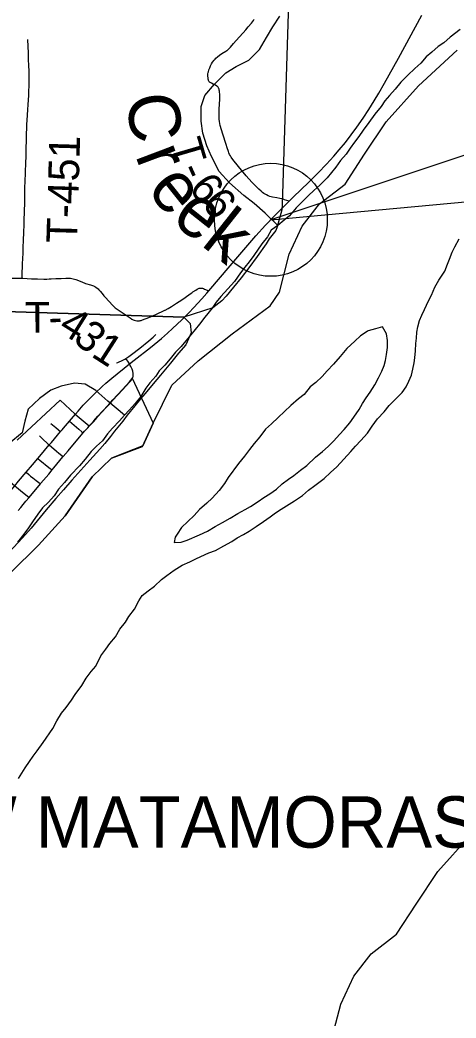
# Model space of a CAD drawing. Extents: x 6.3 to 40.3, y 9 to 31.
# Drawn here: x 11.78 to 12.585, y 24.889 to 26.729 of the extents above; entities that cross this region are included whole.
import ezdxf

# ---------------------------------------------------------------- set-up
doc = ezdxf.new("R2010")
doc.units = 0
for name, color, linetype in [('Default', 7, 'Continuous'), ('GM_X_City_Street', 7, 'Continuous'), ('GM_X_Corporation', 7, 'Continuous'), ('GM_X_Corporation_Text', 7, 'Continuous'), ('GM_X_Major_River', 7, 'Continuous'), ('GM_X_Minor_River', 7, 'Continuous'), ('GM_X_Minor_River_Text', 7, 'Continuous'), ('GM_X_Section', 7, 'Continuous'), ('GM_X_State_Route', 7, 'Continuous'), ('GM_X_Township_Road', 7, 'Continuous'), ('GM_X_Township_Road_Text', 7, 'Continuous'), ('SH_Cut_Line', 7, 'Continuous'), ('TX_P_1', 7, 'Continuous')]:
    doc.layers.add(name, color=color, linetype=linetype)

msp = doc.modelspace()

# ---------------------------------------------------------------- linework, layer by layer
at = {"layer": 'Default'}
for points in [[(11.7623, 25.7099), (11.814, 25.7608), (11.8637, 25.8147), (11.9131, 25.8868), (11.949, 25.9211), (12.0064, 25.9429), (12.0259, 25.9857), (12.0606, 26.0557), (12.1089, 26.1009), (12.1716, 26.1508), (12.2422, 26.2023), (12.2589, 26.2273), (12.2772, 26.2974), (12.3007, 26.349), (12.3328, 26.3901), (12.3801, 26.4265), (12.4161, 26.4817), (12.4558, 26.5416), (12.5156, 26.6082), (12.5871, 26.6738)], [(12.3542, 24.8446), (12.3726, 24.9147), (12.3961, 24.9663), (12.4281, 25.0074), (12.4754, 25.0438), (12.5114, 25.0991), (12.5512, 25.1589), (12.6109, 25.2255)]]:
    msp.add_lwpolyline(points, dxfattribs=at)
at = {"layer": 'GM_X_City_Street'}
for points in [[(11.8714, 25.9895), (11.8758, 25.9857), (11.8884, 25.975), (11.8945, 25.9698), (11.8968, 25.9679)], [(11.7768, 25.8248), (11.7815, 25.8304), (11.7859, 25.8356), (11.791, 25.8418), (11.797, 25.8489), (11.7993, 25.8517), (11.8059, 25.8598), (11.8177, 25.8739), (11.8186, 25.875), (11.833, 25.8921), (11.8392, 25.8995), (11.8426, 25.9035), (11.8594, 25.9235), (11.8599, 25.9241), (11.8688, 25.935), (11.887, 25.9563), (11.8968, 25.9679), (11.8994, 25.9709), (11.9053, 25.9774), (11.908, 25.9804)], [(11.837, 25.985), (11.8464, 25.9776), (11.8512, 25.9736), (11.855, 25.9704)], [(11.8158, 25.9625), (11.8212, 25.9574), (11.8323, 25.9474), (11.8342, 25.9457), (11.8473, 25.9344), (11.852, 25.9305), (11.8571, 25.9264), (11.8599, 25.9241)], [(11.8128, 25.9206), (11.8172, 25.9169), (11.8196, 25.915), (11.8301, 25.9065), (11.8359, 25.902), (11.8392, 25.8995)], [(11.746, 25.89), (11.7467, 25.8899), (11.7473, 25.8897), (11.7483, 25.8891), (11.749, 25.8885), (11.7618, 25.8776), (11.7704, 25.8704), (11.7737, 25.8676), (11.7809, 25.8617), (11.7877, 25.8564), (11.7932, 25.852), (11.797, 25.8489)], [(11.7914, 25.8953), (11.7961, 25.8914), (11.7996, 25.8884), (11.804, 25.885), (11.8097, 25.8804), (11.8147, 25.8764), (11.8177, 25.8739)]]:
    msp.add_lwpolyline(points, dxfattribs=at)
at = {"layer": 'GM_X_Corporation'}
msp.add_lwpolyline([(11.775, 25.9545), (11.8544, 26.0285), (11.8821, 26.0027), (11.9078, 25.9809), (11.9103, 25.9835), (11.912, 25.9852), (11.9149, 25.9884), (11.9197, 25.9939), (11.9238, 25.9985), (11.9318, 26.0072), (11.9439, 26.0205), (11.9514, 26.0287), (11.9692, 26.0478), (11.9821, 26.062), (11.9848, 26.0653), (11.9863, 26.0673), (11.9871, 26.0687), (12.0259, 25.9857), (12.0067, 25.9443), (11.955, 25.9235), (11.949, 25.9211), (11.9131, 25.8868), (11.8637, 25.8147), (11.814, 25.7608), (11.7623, 25.7099)], dxfattribs=at)
at = {"layer": 'GM_X_Major_River'}
for points in [[(12.5927, 26.7118), (12.574, 26.6974), (12.5624, 26.6874), (12.5523, 26.6804), (12.5407, 26.6703), (12.5299, 26.6614), (12.5202, 26.6498), (12.509, 26.6397), (12.4963, 26.6277), (12.4833, 26.6146), (12.4725, 26.6019), (12.4621, 26.59), (12.4536, 26.5803), (12.4469, 26.57), (12.4354, 26.5557), (12.4239, 26.5403), (12.4136, 26.5261), (12.4058, 26.5142), (12.3976, 26.5038), (12.3895, 26.493), (12.3821, 26.4819), (12.3717, 26.47), (12.3632, 26.4577), (12.3554, 26.448), (12.3472, 26.4384), (12.3338, 26.4245), (12.3226, 26.4152), (12.3129, 26.4059), (12.3025, 26.3951), (12.2902, 26.3831), (12.2779, 26.3681), (12.2679, 26.36), (12.2563, 26.3503), (12.2435, 26.3417), (12.2369, 26.3294), (12.2265, 26.3164), (12.2118, 26.2949), (12.2029, 26.2833), (12.1954, 26.2733), (12.1869, 26.2629), (12.1758, 26.2468), (12.1639, 26.2337), (12.1509, 26.2194), (12.142, 26.209), (12.1346, 26.1979), (12.1216, 26.1813), (12.1112, 26.1682), (12.1034, 26.1586), (12.0956, 26.1486), (12.0864, 26.1378), (12.0774, 26.127), (12.067, 26.1166), (12.0574, 26.1043), (12.0473, 26.0931), (12.0369, 26.0823), (12.031, 26.0723), (12.0199, 26.0604), (12.0121, 26.0504), (12.0029, 26.035), (11.9928, 26.0223), (11.9817, 26.01), (11.9731, 26.0004), (11.9635, 25.9903), (11.9508, 25.9764), (11.9415, 25.966), (11.9323, 25.9533), (11.9214, 25.9437), (11.9114, 25.9336), (11.9002, 25.9194), (11.8902, 25.9071), (11.8731, 25.8897), (11.862, 25.8762), (11.8512, 25.8643), (11.843, 25.8516), (11.8326, 25.8404), (11.8218, 25.8296)], [(11.9561, 25.592), (11.9645, 25.6058), (11.9749, 25.6189), (11.9812, 25.6292), (11.9916, 25.6427), (11.9996, 25.658), (12.0055, 25.668), (12.0164, 25.6769), (12.0284, 25.6851), (12.041, 25.6978), (12.0511, 25.7048), (12.0646, 25.7145), (12.0796, 25.7239), (12.0939, 25.7302), (12.1044, 25.7354), (12.1142, 25.7397), (12.1289, 25.7468), (12.1409, 25.7512), (12.1563, 25.7598), (12.1714, 25.7677), (12.1811, 25.7747), (12.1928, 25.7806), (12.2029, 25.7868), (12.216, 25.7954), (12.2299, 25.8044), (12.2422, 25.8134), (12.252, 25.8204), (12.2621, 25.827), (12.2771, 25.8367), (12.2868, 25.8426), (12.3014, 25.8527), (12.3126, 25.862), (12.3246, 25.8706), (12.3418, 25.8838), (12.3534, 25.895), (12.365, 25.9055), (12.378, 25.9194), (12.3906, 25.9336), (12.3992, 25.9436), (12.4092, 25.9537), (12.4215, 25.9676), (12.4304, 25.9806), (12.44, 25.9937), (12.4527, 26.0068), (12.4616, 26.0184), (12.4757, 26.0327), (12.4854, 26.0423), (12.4928, 26.0531), (12.4979, 26.063), (12.5027, 26.0745), (12.5055, 26.0852), (12.5076, 26.097), (12.5089, 26.1065), (12.5102, 26.1194), (12.5111, 26.1327), (12.5121, 26.1429), (12.513, 26.1536), (12.5147, 26.1635), (12.5179, 26.1749), (12.5219, 26.1848), (12.5267, 26.1955), (12.5344, 26.2116), (12.5395, 26.2216), (12.5461, 26.2365), (12.5534, 26.2495), (12.5641, 26.266), (12.5692, 26.279), (12.5732, 26.2885), (12.5779, 26.3012), (12.583, 26.3111), (12.5911, 26.3257)], [(12.0666, 25.7756), (12.0645, 25.7661), (12.0774, 25.7667), (12.0887, 25.7704), (12.1112, 25.7799), (12.1263, 25.7866), (12.1402, 25.7952), (12.1537, 25.8026), (12.1683, 25.8109), (12.1822, 25.8195), (12.1957, 25.8265), (12.2055, 25.8324), (12.2197, 25.8414), (12.2302, 25.8488), (12.2411, 25.8558), (12.2538, 25.8644), (12.2639, 25.874), (12.2755, 25.8826), (12.2856, 25.8892), (12.298, 25.8993), (12.3099, 25.9079), (12.3256, 25.923), (12.3387, 25.9334), (12.3491, 25.9431), (12.3596, 25.9532), (12.37, 25.9647), (12.3785, 25.9744), (12.3893, 25.9867), (12.3963, 25.9967), (12.406, 26.0109), (12.4126, 26.0224), (12.4192, 26.0328), (12.4266, 26.0431), (12.4351, 26.0566), (12.4417, 26.0696), (12.4483, 26.0818), (12.4523, 26.0922), (12.4548, 26.1017), (12.4569, 26.1127), (12.4585, 26.1253), (12.4587, 26.1382), (12.457, 26.1503), (12.4495, 26.1634), (12.4363, 26.1601), (12.4231, 26.1562)], [(12.4231, 26.1562), (12.4212, 26.1549), (12.4089, 26.1471), (12.3984, 26.1371), (12.3835, 26.1235), (12.3712, 26.1089), (12.359, 26.0946), (12.3471, 26.0823), (12.3378, 26.0719), (12.3262, 26.061), (12.3157, 26.0529), (12.305, 26.039), (12.2941, 26.0309), (12.2803, 26.0185), (12.2684, 26.0073), (12.2564, 25.9964), (12.2441, 25.9848), (12.2333, 25.9748), (12.2229, 25.9609), (12.2125, 25.9486), (12.2036, 25.9374), (12.1944, 25.9247), (12.1832, 25.9116), (12.1644, 25.8855), (12.1574, 25.8744), (12.1477, 25.8617), (12.1347, 25.8478), (12.125, 25.8385), (12.1116, 25.8265), (12.1015, 25.8153), (12.09, 25.8045), (12.0784, 25.7933), (12.0703, 25.781), (12.0666, 25.7756)], [(11.8218, 25.8296), (11.8129, 25.8181), (11.8033, 25.8038), (11.7956, 25.7927), (11.7874, 25.7812), (11.7755, 25.7662)], [(11.7775, 25.3308), (11.7893, 25.3504), (11.7978, 25.3619), (11.8041, 25.3715), (11.8119, 25.3819), (11.823, 25.3969), (11.8407, 25.423), (11.8481, 25.4368), (11.8569, 25.451), (11.8651, 25.4617), (11.8751, 25.4752), (11.8817, 25.4852), (11.8943, 25.5021), (11.9021, 25.5155), (11.9117, 25.5282), (11.9202, 25.5378), (11.929, 25.557), (11.9383, 25.5689), (11.946, 25.5796), (11.9561, 25.592)]]:
    msp.add_lwpolyline(points, dxfattribs=at)
at = {"layer": 'GM_X_Minor_River'}
for points in [[(12.2563, 26.3503), (12.2324, 26.373), (12.2123, 26.3907), (12.193, 26.4055), (12.1669, 26.4289), (12.1476, 26.45), (12.1336, 26.4776), (12.1249, 26.4972), (12.1177, 26.5206), (12.1143, 26.5429), (12.1146, 26.5697), (12.1211, 26.5904), (12.1393, 26.6112), (12.1601, 26.6319), (12.1794, 26.6433), (12.2025, 26.655), (12.2222, 26.675), (12.235, 26.6969), (12.2471, 26.7169), (12.2596, 26.7361)], [(11.9731, 26.0004), (11.942, 26.0262), (11.9201, 26.0462), (11.9004, 26.0575), (11.8807, 26.0598), (11.8561, 26.0538), (11.8368, 26.0466), (11.816, 26.0315), (11.7952, 26.0115), (11.7891, 25.9896), (11.7842, 25.9681), (11.7603, 25.9481)]]:
    msp.add_lwpolyline(points, dxfattribs=at)
at = {"layer": 'GM_X_Section'}
msp.add_lwpolyline([(11.3031, 27.2038), (12.2889, 27.1733), (12.2638, 26.3888), (12.2636, 26.3793), (12.255, 26.3481), (12.2521, 26.3409), (12.2402, 26.3255), (12.2343, 26.3163), (12.218, 26.293), (12.2028, 26.2726), (12.1883, 26.2538), (12.1742, 26.2366), (12.1608, 26.2201), (12.1526, 26.2116), (12.1361, 26.1988), (12.0826, 26.1813), (11.2666, 26.2073)], close=True, dxfattribs=at)
msp.add_lwpolyline([(11.2666, 26.2073), (12.0826, 26.1813), (12.0945, 26.1697), (12.0959, 26.1527), (12.086, 26.1306), (12.0726, 26.1148), (12.0578, 26.0968), (12.0392, 26.0745), (12.0262, 26.0584), (12.0113, 26.0407), (12.0027, 26.0307), (11.992, 26.0176), (11.9778, 26.0004), (11.9697, 25.9896), (11.9548, 25.9708), (11.947, 25.9612), (11.9366, 25.9482), (11.9277, 25.9382), (11.909, 25.9178), (11.8755, 25.8809), (11.8603, 25.8628), (11.8465, 25.8467), (11.8286, 25.8259), (11.8004, 25.7921), (11.7847, 25.7745), (11.7598, 25.7479)], dxfattribs=at)
at = {"layer": 'GM_X_State_Route'}
for points in [[(11.8823, 26.0022), (11.8876, 26.0082), (11.8969, 26.019), (11.9076, 26.0304), (11.9186, 26.0414), (11.9318, 26.0537), (11.9383, 26.0595), (11.9493, 26.0686), (11.9823, 26.095), (11.991, 26.102), (12.0208, 26.1255), (12.041, 26.142), (12.0523, 26.1517), (12.0619, 26.1605), (12.0786, 26.1763), (12.0918, 26.1894), (12.1012, 26.1993), (12.116, 26.2153), (12.125, 26.2255), (12.1285, 26.2297), (12.1858, 26.2969), (12.2156, 26.3312), (12.2336, 26.3509), (12.2495, 26.3676), (12.2683, 26.3866), (12.277, 26.395), (12.2853, 26.4031), (12.313, 26.4298), (12.3305, 26.4474), (12.346, 26.4635), (12.3595, 26.4781), (12.3696, 26.4898), (12.3807, 26.5033), (12.3917, 26.5175), (12.402, 26.5315), (12.4137, 26.5483), (12.4243, 26.5643), (12.4342, 26.5801), (12.4427, 26.5945), (12.4532, 26.6129), (12.4788, 26.6591), (12.5221, 26.7381)], [(11.8576, 25.9735), (11.8601, 25.9765), (11.8714, 25.9895), (11.8823, 26.0022)], [(11.6779, 25.7693), (11.6969, 25.7894), (11.6995, 25.7921), (11.7212, 25.8151), (11.7384, 25.8331), (11.7469, 25.8426), (11.7495, 25.8456), (11.7704, 25.8704), (11.7775, 25.8789), (11.7914, 25.8953), (11.8032, 25.9091), (11.8128, 25.9206), (11.8168, 25.9253), (11.8342, 25.9457), (11.8381, 25.9504), (11.855, 25.9704), (11.8576, 25.9735)]]:
    msp.add_lwpolyline(points, dxfattribs=at)
at = {"layer": 'GM_X_Township_Road'}
for points in [[(12.1482, 26.5714), (12.1487, 26.586), (12.1488, 26.591), (12.1487, 26.5934), (12.1485, 26.5959), (12.1483, 26.598), (12.148, 26.6), (12.1476, 26.6016), (12.1472, 26.6029), (12.1468, 26.6037), (12.1464, 26.6045), (12.1458, 26.6053), (12.1452, 26.606), (12.1442, 26.607), (12.1435, 26.6076), (12.1428, 26.6081), (12.1396, 26.6099), (12.1365, 26.6113), (12.1335, 26.6126), (12.131, 26.6139), (12.1302, 26.6145), (12.1296, 26.615), (12.1291, 26.6157), (12.1286, 26.6165), (12.1282, 26.6175), (12.128, 26.6185), (12.1276, 26.6203), (12.1272, 26.6231), (12.127, 26.6248), (12.127, 26.6265), (12.1269, 26.6285), (12.1271, 26.6302), (12.1275, 26.6324), (12.1279, 26.6339), (12.1289, 26.6372), (12.1303, 26.6413), (12.1318, 26.6447), (12.1337, 26.6483), (12.1357, 26.6514), (12.1387, 26.6553), (12.1402, 26.6571), (12.1418, 26.6588), (12.1449, 26.6615), (12.1486, 26.6645), (12.1529, 26.6674), (12.1602, 26.6718), (12.1619, 26.673), (12.1633, 26.674), (12.1648, 26.6754), (12.1686, 26.6795), (12.1744, 26.6857), (12.1848, 26.6975), (12.1918, 26.7056), (12.1967, 26.7113), (12.2015, 26.7168), (12.2072, 26.7236), (12.2093, 26.7261), (12.2112, 26.7285), (12.2126, 26.7308)], [(11.7894, 26.4313), (11.7895, 26.4344), (11.7901, 26.4447), (11.7905, 26.4532), (11.7909, 26.4618), (11.7911, 26.4692), (11.7912, 26.4748), (11.7916, 26.4878), (11.7929, 26.5366), (11.7933, 26.5446), (11.7943, 26.5637), (11.795, 26.5736), (11.7961, 26.5901), (11.7965, 26.5988), (11.7968, 26.6074), (11.7971, 26.618), (11.7971, 26.626), (11.7969, 26.6347), (11.7964, 26.6452), (11.796, 26.6565), (11.7957, 26.6683), (11.7942, 26.6933)], [(12.277, 26.395), (12.2685, 26.3979), (12.2661, 26.3987), (12.2639, 26.3993), (12.2596, 26.4002), (12.254, 26.4012), (12.2462, 26.4028), (12.2416, 26.4041), (12.2383, 26.4053), (12.2351, 26.4067), (12.2329, 26.4079), (12.2305, 26.4092), (12.2278, 26.4113), (12.2251, 26.4134), (12.2209, 26.4174), (12.2152, 26.4231), (12.2081, 26.4304), (12.1978, 26.4417), (12.1835, 26.4593), (12.1732, 26.4722), (12.1701, 26.4765), (12.1687, 26.4788), (12.1671, 26.4815), (12.1659, 26.4842), (12.1649, 26.4868), (12.1627, 26.4933), (12.1606, 26.4995), (12.1545, 26.5185), (12.1499, 26.5348), (12.149, 26.5385), (12.1483, 26.542), (12.1479, 26.5464), (12.1477, 26.5494), (12.1476, 26.5521), (12.1477, 26.558), (12.148, 26.5673), (12.1482, 26.5714)], [(11.784, 26.253), (11.7841, 26.2579), (11.7849, 26.2796), (11.7856, 26.2994), (11.7861, 26.31), (11.7867, 26.3236), (11.7873, 26.3372), (11.7877, 26.3521), (11.7879, 26.3601), (11.7884, 26.3755), (11.7887, 26.3933), (11.789, 26.4129), (11.7891, 26.4202), (11.7894, 26.4313)], [(11.7297, 26.2542), (11.7391, 26.2542), (11.7503, 26.2538), (11.7639, 26.2535), (11.7776, 26.2532), (11.784, 26.253)], [(11.784, 26.253), (11.785, 26.253), (11.8011, 26.2522), (11.8123, 26.2518), (11.8241, 26.2516), (11.8297, 26.2517), (11.834, 26.2518), (11.8377, 26.252), (11.8464, 26.2524), (11.8562, 26.2529), (11.8649, 26.2532), (11.8704, 26.2532), (11.8733, 26.253), (11.8755, 26.2527), (11.8784, 26.252), (11.8831, 26.2505), (11.8941, 26.2462), (11.9011, 26.2437), (11.9099, 26.241), (11.9159, 26.2388), (11.918, 26.2377), (11.9202, 26.2364), (11.9223, 26.2349), (11.9242, 26.2334), (11.9258, 26.2317), (11.9283, 26.229), (11.9317, 26.2248), (11.9351, 26.2207), (11.9373, 26.2182), (11.9515, 26.2031), (11.9542, 26.2003), (11.9559, 26.1988), (11.9576, 26.1975), (11.9706, 26.1884), (11.9832, 26.1798), (11.9864, 26.1779), (11.9888, 26.1766), (11.9907, 26.1759), (11.9931, 26.1752), (11.9956, 26.1748), (11.9982, 26.1747), (12.0004, 26.1747), (12.002, 26.175), (12.0036, 26.1754), (12.0062, 26.1762), (12.0178, 26.1805), (12.0311, 26.1862), (12.0472, 26.194), (12.0481, 26.1944)], [(12.0481, 26.1944), (12.0538, 26.1973), (12.06, 26.2008), (12.0689, 26.2069), (12.0742, 26.2102), (12.0808, 26.2145), (12.0916, 26.2223), (12.0945, 26.2245), (12.0975, 26.2264), (12.0994, 26.2279), (12.1044, 26.2313), (12.1074, 26.2331), (12.1086, 26.2338), (12.1099, 26.2342), (12.1111, 26.2345), (12.1125, 26.2347), (12.1138, 26.2348), (12.1153, 26.2347), (12.1167, 26.2345), (12.118, 26.2342), (12.1191, 26.2339), (12.1207, 26.2331), (12.1285, 26.2297)], [(11.9752, 26.1051), (11.981, 26.1087), (11.9861, 26.1123), (12.0012, 26.1243), (12.0176, 26.1377), (12.0256, 26.1446), (12.0306, 26.1493)], [(11.9584, 26.0973), (11.9607, 26.098), (11.9631, 26.0989), (11.9676, 26.1009), (11.9736, 26.1041), (11.9752, 26.1051)], [(11.9823, 26.095), (11.9802, 26.0984), (11.9792, 26.0999), (11.9773, 26.1024), (11.9752, 26.1051)], [(11.9873, 26.0681), (11.9882, 26.07), (11.9885, 26.0709), (11.9887, 26.0718), (11.9889, 26.0732), (11.9891, 26.0748), (11.9891, 26.0761), (11.989, 26.0773), (11.9888, 26.0785), (11.9886, 26.0799), (11.9882, 26.0815), (11.9876, 26.0837), (11.9869, 26.0856), (11.9865, 26.0868), (11.9859, 26.088), (11.9849, 26.0901), (11.9836, 26.0925), (11.9823, 26.095)], [(11.9381, 26.0133), (11.9441, 26.0199), (11.9516, 26.0282), (11.9694, 26.0472), (11.9823, 26.0615), (11.985, 26.0648), (11.9865, 26.0668), (11.9873, 26.0681)], [(11.908, 25.9804), (11.9105, 25.9829), (11.9122, 25.9847), (11.9151, 25.9878), (11.9199, 25.9934), (11.924, 25.998), (11.932, 26.0066), (11.9381, 26.0133)]]:
    msp.add_lwpolyline(points, dxfattribs=at)
at = {"layer": 'SH_Cut_Line'}
msp.add_lwpolyline([(11.7623, 25.7099), (11.814, 25.7608), (11.8637, 25.8147), (11.9131, 25.8868), (11.949, 25.9211), (12.0064, 25.9429), (12.0259, 25.9857), (12.0606, 26.0557), (12.1089, 26.1009), (12.1716, 26.1508), (12.2422, 26.2023), (12.2589, 26.2273), (12.2772, 26.2974), (12.3007, 26.349), (12.3328, 26.3901), (12.3801, 26.4265), (12.4161, 26.4817), (12.4558, 26.5416), (12.5156, 26.6082), (12.5871, 26.6738)], dxfattribs=at)
at = {"layer": 'TX_P_1'}
msp.add_lwpolyline([(13.2665, 26.7014), (12.2432, 26.3609), (13.2665, 26.4555)], close=True, dxfattribs=at)
msp.add_circle((12.2432, 26.3609), 0.1042, dxfattribs=at)

# ---------------------------------------------------------------- texts
at = {"layer": 'GM_X_Corporation_Text'}
msp.add_text('NEW MATAMORAS', height=0.094697, rotation=0, dxfattribs=at).set_placement((11.4786, 25.2031))
at = {"layer": 'GM_X_Minor_River_Text'}
for s, rotation, p in [('C', 277.6127, (11.9756, 26.5892)), ('r', 290.6122, (11.9922, 26.4804)), ('e', 308.6101, (12.0128, 26.4167)), ('ek', 321.6082, (12.0571, 26.3587))]:
    msp.add_text(s, height=0.0947, rotation=rotation, dxfattribs=at).set_placement(p)
at = {"layer": 'GM_X_Township_Road_Text'}
for s, height, rotation, p in [('T-451', 0.05682, 88.3396, (11.8854, 26.3172)), ('T', 0.0568, 286.2898, (12.0575, 26.502)), ('-', 0.0568, 294.3976, (12.0724, 26.453)), ('6', 0.0568, 308.5624, (12.09, 26.4187)), ('6', 0.0568, 310.9501, (12.1135, 26.3894)), ('T', 0.0568, 0.5622, (11.7892, 26.1523)), ('-', 0.0568, 2.6135, (11.8339, 26.1528)), ('4', 0.0568, 328.0489, (11.8483, 26.1561)), ('3', 0.0568, 318.0896, (11.8757, 26.1393)), ('1', 0.0568, 327.2726, (11.9094, 26.1101))]:
    msp.add_text(s, height=height, rotation=rotation, dxfattribs=at).set_placement(p)

doc.saveas('drawing.dxf')
